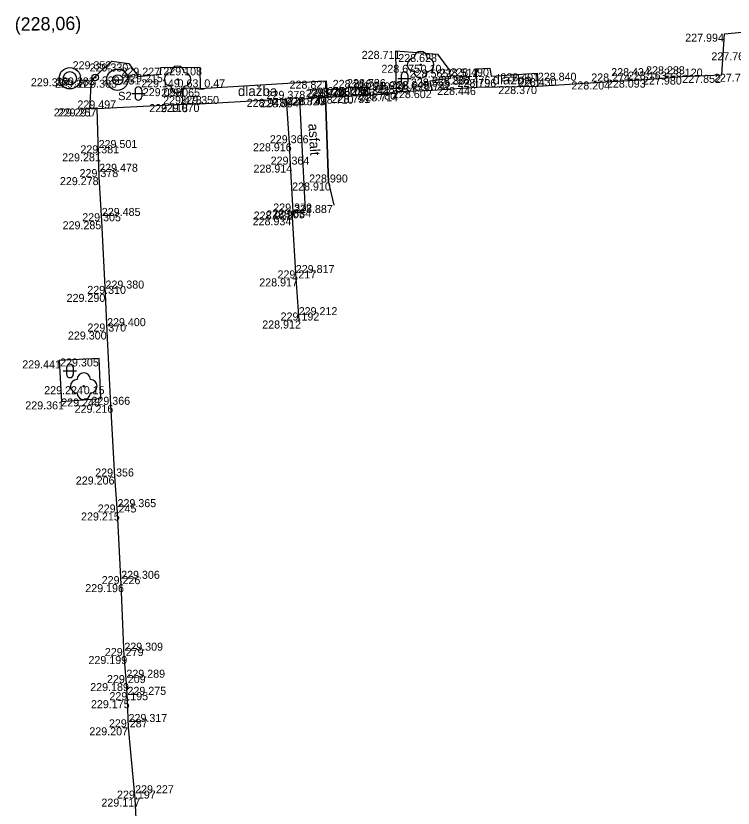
# Model space of a CAD drawing. Extents: x -599516 to -599132, y -1163668 to -1163119.
# Drawn here: x -599432 to -599405.11, y -1163270.22 to -1163240.53 of the extents above; entities that cross this region are included whole.
import ezdxf

# ---------------------------------------------------------------- set-up
doc = ezdxf.new("R2010")
doc.units = 0
for name, color, linetype in [('Bod-oznac1', 7, 'Continuous'), ('Bod-oznac2', 7, 'Continuous'), ('Bod-oznac3', 7, 'Continuous'), ('Bod-vyska1', 7, 'Continuous'), ('Bod-vyska2', 7, 'Continuous'), ('Bod-vyska3', 7, 'Continuous'), ('Z_cela-hrobu-dolni-linie', 7, 'Continuous'), ('Z_cela-hrobu-horni-linie', 7, 'Continuous'), ('Z_chodnik', 7, 'Continuous'), ('Z_komunikace', 7, 'Continuous'), ('Z_kultury-znacky', 7, 'Continuous'), ('Z_nove-stromy-prumer-kmene', 7, 'Continuous'), ('Z_obvod-kmene-spodek-ve-vysce1_2m', 7, 'Continuous'), ('Z_obvod-skruze', 7, 'Continuous'), ('Z_obvod-skruze-cislo-foto', 7, 'Continuous'), ('Z_podzemni-obrys-sachty', 7, 'Continuous'), ('Z_popis-budov-povrchu', 7, 'Continuous'), ('Z_povrchy-rozhrani-typu', 7, 'Continuous'), ('Z_stromy-kere', 7, 'Continuous'), ('Z_stromy-nove-vysazene', 7, 'Continuous'), ('Z_voda-znacky-sachta', 7, 'Continuous'), ('Z_vodovod-bez-rozliseni', 7, 'Continuous'), ('Z_vodovodni-trubka', 7, 'Continuous'), ('Z_znacky-ostatni-skruz', 7, 'Continuous'), ('Z_zpevnene-plochy', 7, 'Continuous')]:
    doc.layers.add(name, color=color, linetype=linetype)

msp = doc.modelspace()

# ---------------------------------------------------------------- linework, layer by layer
at = {"layer": 'Bod-oznac1'}
for p, q in [((-599405.435, -1163241.196), (-599405.435, -1163241.196)), ((-599417.76, -1163241.84), (-599417.76, -1163241.84)), ((-599428.402, -1163242.229), (-599428.402, -1163242.229)), ((-599416.194, -1163241.958), (-599416.194, -1163241.958)), ((-599427.768, -1163242.312), (-599427.768, -1163242.312)), ((-599426.571, -1163242.469), (-599426.571, -1163242.469)), ((-599425.109, -1163242.455), (-599425.109, -1163242.455)), ((-599416.826, -1163242.362), (-599416.826, -1163242.362)), ((-599414.729, -1163242.513), (-599414.729, -1163242.513)), ((-599414.235, -1163242.492), (-599414.235, -1163242.492)), ((-599427.414, -1163242.8), (-599427.414, -1163242.8)), ((-599426.575, -1163242.714), (-599426.575, -1163242.714)), ((-599415.766, -1163242.539), (-599415.766, -1163242.539)), ((-599414.177, -1163242.79), (-599414.177, -1163242.79)), ((-599412.451, -1163242.68), (-599412.451, -1163242.68)), ((-599407.017, -1163242.803), (-599407.017, -1163242.803)), ((-599405.534, -1163242.74), (-599405.534, -1163242.74)), ((-599429.977, -1163242.867), (-599429.977, -1163242.867)), ((-599429.159, -1163242.921), (-599429.159, -1163242.921)), ((-599429.024, -1163242.836), (-599429.024, -1163242.836)), ((-599428.192, -1163242.921), (-599428.192, -1163242.921)), ((-599425.939, -1163242.907), (-599425.939, -1163242.907)), ((-599420.362, -1163242.957), (-599420.362, -1163242.957)), ((-599416.478, -1163242.97), (-599416.478, -1163242.97)), ((-599415.71, -1163242.876), (-599415.71, -1163242.876)), ((-599409.682, -1163242.987), (-599409.682, -1163242.987)), ((-599408.373, -1163242.917), (-599408.373, -1163242.917)), ((-599425.785, -1163243.237), (-599425.785, -1163243.237)), ((-599425.09, -1163243.252), (-599425.09, -1163243.252)), ((-599419.439, -1163243.227), (-599419.439, -1163243.227)), ((-599418.849, -1163243.197), (-599418.849, -1163243.197)), ((-599417.716, -1163243.366), (-599417.716, -1163243.366)), ((-599416.395, -1163243.311), (-599416.395, -1163243.311)), ((-599414.713, -1163243.195), (-599414.713, -1163243.195)), ((-599412.434, -1163243.159), (-599412.434, -1163243.159)), ((-599421.865, -1163243.638), (-599421.865, -1163243.638)), ((-599421.361, -1163243.657), (-599421.361, -1163243.657)), ((-599420.396, -1163243.579), (-599420.396, -1163243.579)), ((-599420.33, -1163243.573), (-599420.33, -1163243.573)), ((-599419.416, -1163243.519), (-599419.416, -1163243.519)), ((-599418.791, -1163243.494), (-599418.791, -1163243.494)), ((-599417.731, -1163243.43), (-599417.731, -1163243.43)), ((-599429.224, -1163243.998), (-599429.224, -1163243.998)), ((-599428.957, -1163243.998), (-599428.957, -1163243.998)), ((-599425.738, -1163243.836), (-599425.738, -1163243.836)), ((-599425.101, -1163243.829), (-599425.101, -1163243.829)), ((-599421.755, -1163245.302), (-599421.755, -1163245.302)), ((-599428.899, -1163245.681), (-599428.899, -1163245.681)), ((-599421.713, -1163246.103), (-599421.713, -1163246.103)), ((-599428.877, -1163246.571), (-599428.877, -1163246.571)), ((-599420.28, -1163246.773), (-599420.28, -1163246.773)), ((-599421.615, -1163247.861), (-599421.615, -1163247.861)), ((-599421.15, -1163247.819), (-599421.15, -1163247.819)), ((-599420.086, -1163247.617), (-599420.086, -1163247.617)), ((-599421.642, -1163248.076), (-599421.642, -1163248.076)), ((-599428.778, -1163248.226), (-599428.778, -1163248.226)), ((-599421.507, -1163250.367), (-599421.507, -1163250.367)), ((-599428.641, -1163250.948), (-599428.641, -1163250.948)), ((-599421.398, -1163251.945), (-599421.398, -1163251.945)), ((-599428.582, -1163252.358), (-599428.582, -1163252.358)), ((-599430.371, -1163253.439), (-599430.371, -1163253.439)), ((-599428.874, -1163253.367), (-599428.874, -1163253.367)), ((-599429.455, -1163254.407), (-599429.455, -1163254.407)), ((-599430.291, -1163254.976), (-599430.291, -1163254.976)), ((-599428.818, -1163254.867), (-599428.818, -1163254.867)), ((-599428.443, -1163255.104), (-599428.443, -1163255.104)), ((-599428.296, -1163257.792), (-599428.296, -1163257.792)), ((-599428.19, -1163259.14), (-599428.19, -1163259.14)), ((-599428.054, -1163261.826), (-599428.054, -1163261.826)), ((-599427.934, -1163264.52), (-599427.934, -1163264.52)), ((-599427.857, -1163265.533), (-599427.857, -1163265.533)), ((-599427.817, -1163266.174), (-599427.817, -1163266.174)), ((-599427.776, -1163267.192), (-599427.776, -1163267.192)), ((-599427.53, -1163269.863), (-599427.53, -1163269.863))]:
    msp.add_line(p, q, dxfattribs=at)
at = {"layer": 'Bod-oznac2'}
for p, q in [((-599407.017, -1163242.803), (-599407.017, -1163242.803)), ((-599409.682, -1163242.987), (-599409.682, -1163242.987)), ((-599408.373, -1163242.917), (-599408.373, -1163242.917)), ((-599419.439, -1163243.227), (-599419.439, -1163243.227)), ((-599418.849, -1163243.197), (-599418.849, -1163243.197)), ((-599416.395, -1163243.311), (-599416.395, -1163243.311)), ((-599414.713, -1163243.195), (-599414.713, -1163243.195)), ((-599412.434, -1163243.159), (-599412.434, -1163243.159)), ((-599421.865, -1163243.638), (-599421.865, -1163243.638)), ((-599420.396, -1163243.579), (-599420.396, -1163243.579)), ((-599420.33, -1163243.573), (-599420.33, -1163243.573)), ((-599419.416, -1163243.519), (-599419.416, -1163243.519)), ((-599418.791, -1163243.494), (-599418.791, -1163243.494)), ((-599417.731, -1163243.43), (-599417.731, -1163243.43)), ((-599428.957, -1163243.998), (-599428.957, -1163243.998)), ((-599425.738, -1163243.836), (-599425.738, -1163243.836)), ((-599425.101, -1163243.829), (-599425.101, -1163243.829)), ((-599421.755, -1163245.302), (-599421.755, -1163245.302)), ((-599428.899, -1163245.681), (-599428.899, -1163245.681)), ((-599421.713, -1163246.103), (-599421.713, -1163246.103)), ((-599428.877, -1163246.571), (-599428.877, -1163246.571)), ((-599420.28, -1163246.773), (-599420.28, -1163246.773)), ((-599421.615, -1163247.861), (-599421.615, -1163247.861)), ((-599421.642, -1163248.076), (-599421.642, -1163248.076)), ((-599428.778, -1163248.226), (-599428.778, -1163248.226)), ((-599421.507, -1163250.367), (-599421.507, -1163250.367)), ((-599428.641, -1163250.948), (-599428.641, -1163250.948)), ((-599421.398, -1163251.945), (-599421.398, -1163251.945)), ((-599428.582, -1163252.358), (-599428.582, -1163252.358)), ((-599428.443, -1163255.104), (-599428.443, -1163255.104)), ((-599428.296, -1163257.792), (-599428.296, -1163257.792)), ((-599428.19, -1163259.14), (-599428.19, -1163259.14)), ((-599428.054, -1163261.826), (-599428.054, -1163261.826)), ((-599427.934, -1163264.52), (-599427.934, -1163264.52)), ((-599427.857, -1163265.533), (-599427.857, -1163265.533)), ((-599427.817, -1163266.174), (-599427.817, -1163266.174)), ((-599427.776, -1163267.192), (-599427.776, -1163267.192)), ((-599427.53, -1163269.863), (-599427.53, -1163269.863))]:
    msp.add_line(p, q, dxfattribs=at)
at = {"layer": 'Bod-oznac3'}
for p, q in [((-599409.682, -1163242.987), (-599409.682, -1163242.987)), ((-599408.373, -1163242.917), (-599408.373, -1163242.917)), ((-599416.395, -1163243.311), (-599416.395, -1163243.311)), ((-599412.434, -1163243.159), (-599412.434, -1163243.159)), ((-599419.416, -1163243.519), (-599419.416, -1163243.519)), ((-599418.791, -1163243.494), (-599418.791, -1163243.494)), ((-599428.899, -1163245.681), (-599428.899, -1163245.681)), ((-599428.877, -1163246.571), (-599428.877, -1163246.571)), ((-599428.778, -1163248.226), (-599428.778, -1163248.226)), ((-599421.507, -1163250.367), (-599421.507, -1163250.367)), ((-599428.641, -1163250.948), (-599428.641, -1163250.948)), ((-599421.398, -1163251.945), (-599421.398, -1163251.945)), ((-599428.582, -1163252.358), (-599428.582, -1163252.358)), ((-599428.19, -1163259.14), (-599428.19, -1163259.14)), ((-599428.054, -1163261.826), (-599428.054, -1163261.826)), ((-599427.934, -1163264.52), (-599427.934, -1163264.52)), ((-599427.857, -1163265.533), (-599427.857, -1163265.533)), ((-599427.817, -1163266.174), (-599427.817, -1163266.174)), ((-599427.776, -1163267.192), (-599427.776, -1163267.192)), ((-599427.53, -1163269.863), (-599427.53, -1163269.863))]:
    msp.add_line(p, q, dxfattribs=at)
at = {"layer": 'Z_cela-hrobu-dolni-linie'}
msp.add_line((-599428.957, -1163243.998), (-599425.738, -1163243.836), dxfattribs=at)
for points in [[(-599414.713, -1163243.195), (-599412.434, -1163243.159)], [(-599425.101, -1163243.829), (-599421.865, -1163243.638)], [(-599421.865, -1163243.638), (-599421.755, -1163245.302), (-599421.713, -1163246.103), (-599421.615, -1163247.861)]]:
    msp.add_lwpolyline(points, dxfattribs=at)
at = {"layer": 'Z_cela-hrobu-horni-linie'}
for points in [[(-599420.28, -1163246.773), (-599420.396, -1163243.579), (-599419.416, -1163243.519), (-599418.791, -1163243.494), (-599417.731, -1163243.43), (-599417.716, -1163243.366), (-599416.395, -1163243.311), (-599416.395, -1163243.311), (-599414.713, -1163243.195), (-599412.434, -1163243.159), (-599412.434, -1163243.159), (-599409.682, -1163242.987), (-599409.682, -1163242.987), (-599408.373, -1163242.917), (-599408.373, -1163242.917), (-599407.017, -1163242.803)], [(-599425.101, -1163243.829), (-599421.865, -1163243.638), (-599421.755, -1163245.302), (-599421.713, -1163246.103), (-599421.615, -1163247.861)], [(-599427.391, -1163272.632), (-599427.53, -1163269.863), (-599427.53, -1163269.863), (-599427.776, -1163267.192), (-599427.776, -1163267.192), (-599427.817, -1163266.174), (-599427.817, -1163266.174), (-599427.857, -1163265.533), (-599427.857, -1163265.533), (-599427.934, -1163264.52), (-599427.934, -1163264.52), (-599428.054, -1163261.826), (-599428.054, -1163261.826), (-599428.19, -1163259.14), (-599428.19, -1163259.14), (-599428.296, -1163257.792), (-599428.443, -1163255.104), (-599428.582, -1163252.358), (-599428.582, -1163252.358), (-599428.641, -1163250.948), (-599428.641, -1163250.948), (-599428.778, -1163248.226), (-599428.778, -1163248.226), (-599428.877, -1163246.571), (-599428.877, -1163246.571), (-599428.899, -1163245.681), (-599428.899, -1163245.681), (-599428.957, -1163243.998), (-599425.738, -1163243.836)], [(-599421.642, -1163248.076), (-599421.507, -1163250.367), (-599421.507, -1163250.367), (-599421.398, -1163251.945), (-599421.398, -1163251.945)]]:
    msp.add_lwpolyline(points, dxfattribs=at)
at = {"layer": 'Z_chodnik'}
for points in [[(-599420.396, -1163243.579), (-599420.28, -1163246.773), (-599420.086, -1163247.617)], [(-599421.615, -1163247.861), (-599421.642, -1163248.076), (-599421.507, -1163250.367), (-599421.398, -1163251.945)]]:
    msp.add_lwpolyline(points, dxfattribs=at)
at = {"layer": 'Z_komunikace'}
for points in [[(-599420.33, -1163243.573), (-599419.416, -1163243.519), (-599419.439, -1163243.227), (-599418.849, -1163243.197), (-599418.791, -1163243.494), (-599417.731, -1163243.43), (-599417.76, -1163241.84), (-599416.194, -1163241.958), (-599415.766, -1163242.539), (-599415.71, -1163242.876), (-599416.478, -1163242.97), (-599416.395, -1163243.311), (-599414.713, -1163243.195), (-599414.729, -1163242.513), (-599414.235, -1163242.492), (-599414.177, -1163242.79), (-599412.451, -1163242.68), (-599412.434, -1163243.159), (-599409.682, -1163242.987), (-599408.373, -1163242.917), (-599407.017, -1163242.803), (-599405.534, -1163242.74), (-599405.435, -1163241.196), (-599403.579, -1163241.024)], [(-599428.957, -1163243.998), (-599429.224, -1163243.998), (-599429.159, -1163242.921), (-599428.402, -1163242.229), (-599427.768, -1163242.312), (-599427.414, -1163242.8), (-599426.575, -1163242.714), (-599426.571, -1163242.469), (-599425.109, -1163242.455), (-599425.09, -1163243.252), (-599420.362, -1163242.957), (-599420.33, -1163243.573)], [(-599427.391, -1163272.632), (-599427.53, -1163269.863), (-599427.776, -1163267.192), (-599427.817, -1163266.174), (-599427.857, -1163265.533), (-599427.934, -1163264.52), (-599428.054, -1163261.826), (-599428.19, -1163259.14), (-599428.296, -1163257.792), (-599428.443, -1163255.104), (-599428.582, -1163252.358), (-599428.641, -1163250.948), (-599428.778, -1163248.226), (-599428.877, -1163246.571), (-599428.899, -1163245.681), (-599428.957, -1163243.998)], [(-599428.874, -1163253.367), (-599430.371, -1163253.439), (-599430.291, -1163254.976), (-599428.818, -1163254.867), (-599428.874, -1163253.367)]]:
    msp.add_lwpolyline(points, dxfattribs=at)
at = {"layer": 'Z_kultury-znacky'}
for p, q in [((-599417.551, -1163242.756), (-599417.551, -1163243.006)), ((-599417.301, -1163242.756), (-599417.301, -1163243.006)), ((-599417.676, -1163242.881), (-599417.176, -1163242.881)), ((-599427.533, -1163243.312), (-599427.533, -1163243.562)), ((-599427.283, -1163243.312), (-599427.283, -1163243.562)), ((-599427.658, -1163243.437), (-599427.158, -1163243.437)), ((-599430.097, -1163253.712), (-599430.097, -1163253.962)), ((-599429.847, -1163253.712), (-599429.847, -1163253.962)), ((-599430.222, -1163253.837), (-599429.722, -1163253.837))]:
    msp.add_line(p, q, dxfattribs=at)
for centre, start, end in [((-599417.426, -1163242.756), 0, 180), ((-599417.426, -1163243.006), 180, 0), ((-599427.408, -1163243.312), 0, 180), ((-599427.408, -1163243.562), 180, 0), ((-599429.972, -1163253.712), 0, 180), ((-599429.972, -1163253.962), 180, 0)]:
    msp.add_arc(centre, 0.125, start, end, dxfattribs=at)
at = {"layer": 'Z_obvod-skruze'}
msp.add_circle((-599428.192, -1163242.921), 0.4, dxfattribs=at)
at = {"layer": 'Z_podzemni-obrys-sachty'}
msp.add_circle((-599429.977, -1163242.867), 0.4, dxfattribs=at)
at = {"layer": 'Z_povrchy-rozhrani-typu'}
for points in [[(-599421.361, -1163243.657), (-599421.15, -1163247.819), (-599421.615, -1163247.861)], [(-599420.396, -1163243.579), (-599421.361, -1163243.657)]]:
    msp.add_lwpolyline(points, dxfattribs=at)
at = {"layer": 'Z_stromy-kere'}
msp.add_circle((-599425.939, -1163242.907), 0.025, dxfattribs=at)
for centre, start, end in [((-599425.939, -1163242.657), 0, 180), ((-599426.189, -1163242.907), 90, 270), ((-599425.689, -1163242.907), 270, 90), ((-599425.939, -1163243.157), 180, 0)]:
    msp.add_arc(centre, 0.25, start, end, dxfattribs=at)
at = {"layer": 'Z_stromy-nove-vysazene'}
for centre in [(-599416.826, -1163242.362), (-599429.455, -1163254.407)]:
    msp.add_circle(centre, 0.025, dxfattribs=at)
for centre, start, end in [((-599416.826, -1163242.112), 0, 180), ((-599417.076, -1163242.362), 90, 270), ((-599416.576, -1163242.362), 270, 90), ((-599416.826, -1163242.612), 180, 0), ((-599429.455, -1163254.157), 0, 180), ((-599429.705, -1163254.407), 90, 270), ((-599429.205, -1163254.407), 270, 90), ((-599429.455, -1163254.657), 180, 0)]:
    msp.add_arc(centre, 0.25, start, end, dxfattribs=at)
at = {"layer": 'Z_voda-znacky-sachta'}
msp.add_circle((-599429.977, -1163242.867), 0.25, dxfattribs=at)
at = {"layer": 'Z_vodovodni-trubka'}
for radius in [0.125, 0.025, 0.0075]:
    msp.add_circle((-599429.024, -1163242.836), radius, dxfattribs=at)
at = {"layer": 'Z_znacky-ostatni-skruz'}
msp.add_line((-599428.367, -1163242.921), (-599427.992, -1163242.921), dxfattribs=at)
msp.add_circle((-599428.179, -1163242.921), 0.188, dxfattribs=at)
at = {"layer": 'Z_zpevnene-plochy'}
for points in [[(-599420.396, -1163243.579), (-599420.33, -1163243.573), (-599420.362, -1163242.957)], [(-599425.09, -1163243.252), (-599425.785, -1163243.237), (-599425.738, -1163243.836), (-599425.101, -1163243.829)], [(-599419.416, -1163243.519), (-599419.439, -1163243.227), (-599418.849, -1163243.197), (-599418.791, -1163243.494)]]:
    msp.add_lwpolyline(points, dxfattribs=at)

# ---------------------------------------------------------------- texts
at = {"layer": 'Bod-vyska1'}
for s, p in [('227.994', (-599406.907, -1163241.496)), ('228.711', (-599419.035, -1163242.14)), ('227.765', (-599405.926, -1163242.193)), ('229.352', (-599429.872, -1163242.529)), ('228.628', (-599417.664, -1163242.258)), ('229.330', (-599429.236, -1163242.612)), ('229.227', (-599428.043, -1163242.769)), ('229.108', (-599426.473, -1163242.755)), ('228.675', (-599418.298, -1163242.662)), ('228.512', (-599416.107, -1163242.813)), ('228.490', (-599415.715, -1163242.792)), ('229.251', (-599428.78, -1163243.1)), ('229.215', (-599427.941, -1163243.014)), ('228.565', (-599417.236, -1163242.839)), ('228.476', (-599415.66, -1163243.09)), ('228.401', (-599413.838, -1163242.98)), ('227.980', (-599408.487, -1163243.103)), ('227.852', (-599407.017, -1163243.04)), ('227.723', (-599405.829, -1163242.997)), ('229.397', (-599431.438, -1163243.167)), ('229.371', (-599430.527, -1163243.221)), ('229.383', (-599430.494, -1163243.136)), ('229.303', (-599429.66, -1163243.221)), ('229.149', (-599427.305, -1163243.207)), ('228.821', (-599421.74, -1163243.257)), ('228.645', (-599417.959, -1163243.27)), ('228.555', (-599417.192, -1163243.176)), ('228.204', (-599411.173, -1163243.287)), ('228.093', (-599409.841, -1163243.217)), ('229.098', (-599427.242, -1163243.537)), ('229.065', (-599426.547, -1163243.552)), ('228.736', (-599420.911, -1163243.527)), ('228.706', (-599420.319, -1163243.497)), ('228.780', (-599419.197, -1163243.666)), ('228.602', (-599417.863, -1163243.611)), ('228.446', (-599416.206, -1163243.495)), ('228.370', (-599413.915, -1163243.459)), ('228.948', (-599423.346, -1163243.938)), ('228.894', (-599422.843, -1163243.957)), ('228.820', (-599421.876, -1163243.879)), ('228.749', (-599421.813, -1163243.873)), ('228.710', (-599420.794, -1163243.819)), ('228.731', (-599420.17, -1163243.794)), ('228.714', (-599419.122, -1163243.73)), ('229.291', (-599430.579, -1163244.298)), ('229.257', (-599430.429, -1163244.298)), ('229.118', (-599427, -1163244.136)), ('229.070', (-599426.569, -1163244.129)), ('228.916', (-599423.11, -1163245.602)), ('229.281', (-599430.265, -1163245.981)), ('228.914', (-599423.091, -1163246.403)), ('229.278', (-599430.349, -1163246.871)), ('228.910', (-599421.644, -1163247.073)), ('228.922', (-599423.085, -1163248.161)), ('228.905', (-599422.618, -1163248.119)), ('228.887', (-599421.569, -1163247.917)), ('228.934', (-599423.124, -1163248.376)), ('229.285', (-599430.248, -1163248.526)), ('228.917', (-599422.875, -1163250.667)), ('229.290', (-599430.098, -1163251.248)), ('228.912', (-599422.764, -1163252.245)), ('229.300', (-599430.048, -1163252.658)), ('229.441', (-599431.76, -1163253.739)), ('229.305', (-599430.342, -1163253.667)), ('229.224', (-599430.937, -1163254.707)), ('229.361', (-599431.646, -1163255.276)), ('229.248', (-599430.299, -1163255.167)), ('229.216', (-599429.798, -1163255.404)), ('229.206', (-599429.753, -1163258.092)), ('229.215', (-599429.556, -1163259.44)), ('229.196', (-599429.398, -1163262.126)), ('229.199', (-599429.278, -1163264.82)), ('229.189', (-599429.212, -1163265.833)), ('229.175', (-599429.185, -1163266.474)), ('229.207', (-599429.246, -1163267.492)), ('229.117', (-599428.794, -1163270.163))]:
    msp.add_text(s, height=0.3, dxfattribs=at).set_placement(p)
at = {"layer": 'Bod-vyska2'}
for s, p in [('228.120', (-599407.705, -1163242.803)), ('228.274', (-599410.429, -1163242.987)), ('228.163', (-599409.056, -1163242.917)), ('228.816', (-599420.122, -1163243.227)), ('228.786', (-599419.585, -1163243.197)), ('228.934', (-599418.472, -1163243.43)), ('228.742', (-599417.142, -1163243.311)), ('228.796', (-599415.443, -1163243.195)), ('228.430', (-599413.179, -1163243.159)), ('229.378', (-599422.601, -1163243.638)), ('228.970', (-599421.131, -1163243.579)), ('228.779', (-599421.067, -1163243.573)), ('228.790', (-599420.151, -1163243.519)), ('228.811', (-599419.428, -1163243.494)), ('229.497', (-599429.693, -1163243.998)), ('229.478', (-599426.48, -1163243.836)), ('229.350', (-599425.835, -1163243.829)), ('229.366', (-599422.479, -1163245.302)), ('229.381', (-599429.582, -1163245.681)), ('229.364', (-599422.448, -1163246.103)), ('229.378', (-599429.613, -1163246.571)), ('228.990', (-599421.008, -1163246.773)), ('229.372', (-599422.351, -1163247.861)), ('229.834', (-599422.383, -1163248.076)), ('229.305', (-599429.512, -1163248.226)), ('229.217', (-599422.191, -1163250.367)), ('229.310', (-599429.323, -1163250.948)), ('229.192', (-599422.075, -1163251.945)), ('229.370', (-599429.317, -1163252.358)), ('229.366', (-599429.167, -1163255.104)), ('229.356', (-599429.025, -1163257.792)), ('229.245', (-599428.931, -1163259.14)), ('229.226', (-599428.783, -1163261.826)), ('229.279', (-599428.664, -1163264.52)), ('229.209', (-599428.585, -1163265.533)), ('229.195', (-599428.494, -1163266.174)), ('229.287', (-599428.512, -1163267.192)), ('229.197', (-599428.208, -1163269.863))]:
    msp.add_text(s, height=0.3, dxfattribs=at).set_placement(p)
at = {"layer": 'Bod-vyska3'}
for s, p in [('228.434', (-599409.682, -1163242.787)), ('228.233', (-599408.373, -1163242.717)), ('228.802', (-599416.395, -1163243.111)), ('228.840', (-599412.434, -1163242.959)), ('228.940', (-599419.416, -1163243.319)), ('228.941', (-599418.791, -1163243.294)), ('229.501', (-599428.899, -1163245.481)), ('229.478', (-599428.877, -1163246.371)), ('229.485', (-599428.778, -1163248.026)), ('229.817', (-599421.507, -1163250.167)), ('229.380', (-599428.641, -1163250.748)), ('229.212', (-599421.398, -1163251.745)), ('229.400', (-599428.582, -1163252.158)), ('229.365', (-599428.19, -1163258.94)), ('229.306', (-599428.054, -1163261.626)), ('229.309', (-599427.934, -1163264.32)), ('229.289', (-599427.857, -1163265.333)), ('229.275', (-599427.817, -1163265.974)), ('229.317', (-599427.776, -1163266.992)), ('229.227', (-599427.53, -1163269.663))]:
    msp.add_text(s, height=0.3, dxfattribs=at).set_placement(p)
at = {"layer": 'Z_nove-stromy-prumer-kmene'}
for s, p in [('0.10', (-599416.826, -1163242.662)), ('0.15', (-599429.455, -1163254.707))]:
    msp.add_text(s, height=0.3, dxfattribs=at).set_placement(p)
at = {"layer": 'Z_obvod-kmene-spodek-ve-vysce1_2m'}
msp.add_text('0.63_0.47', height=0.3, dxfattribs=at).set_placement((-599425.939, -1163243.207))
at = {"layer": 'Z_obvod-skruze-cislo-foto'}
msp.add_text('S2', height=0.3125, dxfattribs=at).set_placement((-599428.169, -1163243.686))
at = {"layer": 'Z_popis-budov-povrchu'}
for p in [(-599414.13, -1163243.097), (-599423.675, -1163243.533)]:
    msp.add_text('dlažba', height=0.375, dxfattribs=at).set_placement(p)
msp.add_text('asfalt', height=0.375, rotation=273.4503, dxfattribs=at).set_placement((-599421.035, -1163244.576))
at = {"layer": 'Z_vodovod-bez-rozliseni'}
msp.add_text('(228,06) ', height=0.5, rotation=0.8872, dxfattribs=at).set_placement((-599432.038, -1163241.09))

doc.saveas('drawing.dxf')
